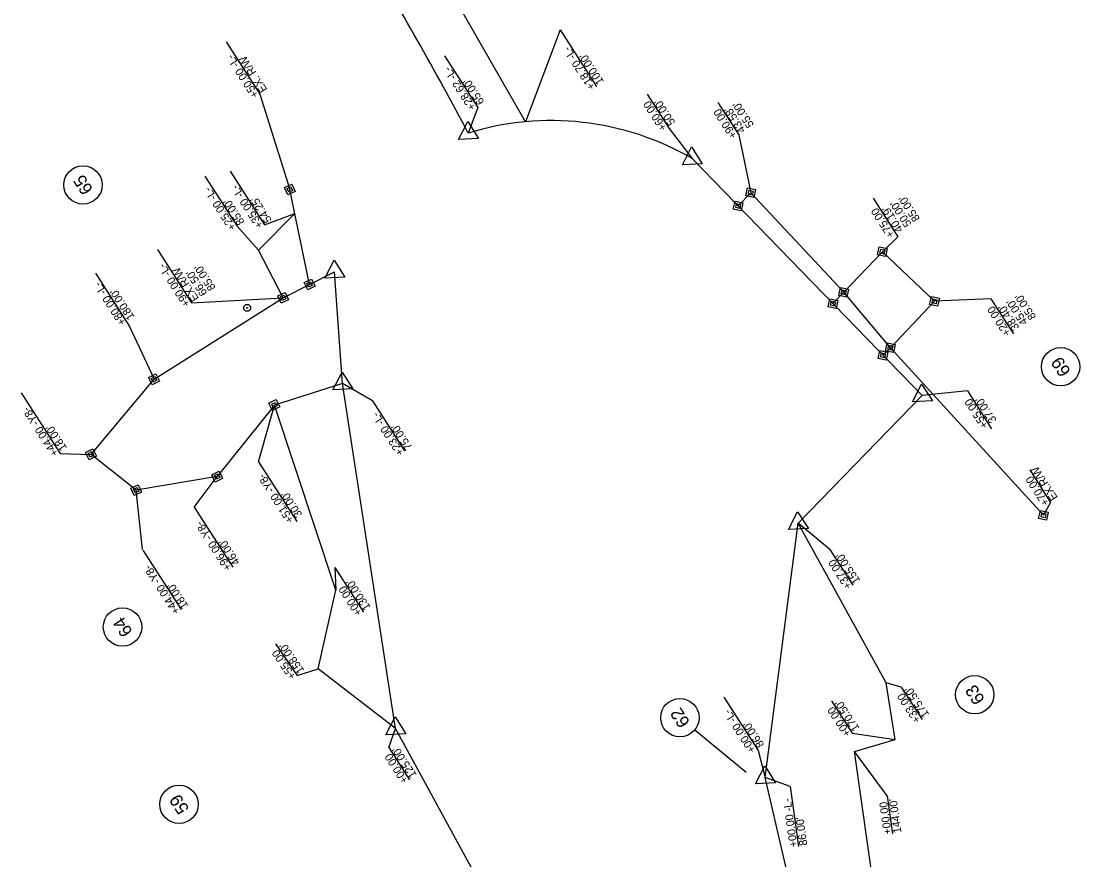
# Model space of a CAD drawing. Extents: x 474184 to 481900, y 489262 to 505659.
# Drawn here: x 477450 to 478112, y 499163 to 499687 of the extents above; entities that cross this region are included whole.
import ezdxf

# ---------------------------------------------------------------- set-up
doc = ezdxf.new("R2010")
doc.units = 0
for name, color, linetype in [('Default', 7, 'Continuous'), ('Prop Drainage Structure Drop Inlet Grate 2 Narrow Slots and Sag Grates 840 24 CELL', 7, 'Continuous'), ('Prop Drainage Structure Drop Inlet Grate 2 Wide Slots and Sag Grates 840 22 CELL', 7, 'Continuous'), ('Prop Drainage Structure Outlet Berm Ditch 850 10 CELL', 7, 'Continuous'), ('Prop Drainage Structure Outlet Berm Ditch 850 10 Label', 7, 'Continuous'), ('Prop Drainage Structure Outlet Generic CELL', 7, 'Continuous'), ('Prop Drainage Structure Pipe CSP 15in', 7, 'Continuous'), ('Prop Drainage Structure Pipe RCP 18in Class IV', 7, 'Continuous'), ('Prop Drainage Structure Pipe RCP 18in Class IV Label', 7, 'Continuous'), ('Prop Drainage Structure Pipe Side Drain 15in Label', 7, 'Continuous'), ('Prop Drainage Structure Pipe Stub Out CELL', 7, 'Continuous'), ('Prop Drainage Structure Plot Symbol 50 Scale', 7, 'Continuous'), ('Prop Earthen Structure Base Ditch Lateral Detail Label', 7, 'Continuous'), ('Prop Earthen Structure False Sump CELL', 7, 'Continuous'), ('Prop Earthen Structure False Sump Label', 7, 'Continuous')]:
    doc.layers.add(name, color=color, linetype=linetype)

msp = doc.modelspace()

# ---------------------------------------------------------------- linework, layer by layer
at = {"layer": 'Default'}
for radius in [2.18, 0.24]:
    msp.add_circle((477591.3, 499507.78), radius, dxfattribs=at)
at = {"layer": 'Prop Drainage Structure Drop Inlet Grate 2 Narrow Slots and Sag Grates 840 24 CELL'}
for p, q in [((477646.75, 499331.16), (477608.32, 499446.99)), ((477635.68, 499281.96), (477646.75, 499331.16)), ((477684.05, 499244.74), (477635.68, 499281.96))]:
    msp.add_line(p, q, dxfattribs=at)
at = {"layer": 'Prop Drainage Structure Drop Inlet Grate 2 Wide Slots and Sag Grates 840 22 CELL'}
for p, q in [((477988.26, 499542.87), (477964.13, 499517.52)), ((478020.86, 499511.85), (477988.26, 499542.87)), ((477613.8, 499514.07), (477645.97, 499530.3)), ((477533.09, 499463.09), (477613.8, 499514.07)), ((477993.28, 499482.87), (478020.86, 499511.85)), ((477493.72, 499416.16), (477533.09, 499463.09)), ((477650.93, 499460.41), (477608.32, 499446.99)), ((477608.32, 499446.99), (477572.54, 499402.26)), ((477521.92, 499393.79), (477493.72, 499416.16)), ((477572.54, 499402.26), (477521.92, 499393.79))]:
    msp.add_line(p, q, dxfattribs=at)
at = {"layer": 'Prop Drainage Structure Outlet Berm Ditch 850 10 CELL'}
for p, q in [((477646, 499345.46), (477663.96, 499317.47)), ((477609.09, 499297.77), (477622.61, 499277.88)), ((477622.61, 499277.88), (477635.68, 499281.96))]:
    msp.add_line(p, q, dxfattribs=at)
msp.add_lwpolyline([(477646, 499345.46), (477646.75, 499331.16)], dxfattribs=at)
at = {"layer": 'Prop Drainage Structure Outlet Berm Ditch 850 10 Label'}
for p, q in [((477630.32, 499522.4), (477617.99, 499581.8)), ((477906.01, 499579.74), (477898.14, 499571.47)), ((477964.13, 499517.52), (477906.01, 499579.74)), ((478088.97, 499378.08), (477993.28, 499482.87))]:
    msp.add_line(p, q, dxfattribs=at)
at = {"layer": 'Prop Drainage Structure Outlet Generic CELL'}
for p, q in [((477964.13, 499517.52), (477957.37, 499510.41)), ((477993.28, 499482.87), (477964.13, 499517.52)), ((477988.73, 499478.09), (477993.28, 499482.87))]:
    msp.add_line(p, q, dxfattribs=at)
at = {"layer": 'Prop Drainage Structure Pipe CSP 15in'}
for p, q in [((477488.71, 499584.64), (477488.71, 499584.64)), ((478099.68, 499470.97), (478099.68, 499470.97)), ((477513.41, 499308.18), (477513.41, 499308.18)), ((478046, 499265.84), (478046, 499265.84)), ((477861.73, 499251.47), (477861.73, 499251.47)), ((477870.99, 499243.84), (477903.14, 499217.42)), ((477548.71, 499197.34), (477548.71, 499197.34))]:
    msp.add_line(p, q, dxfattribs=at)
for centre in [(477488.71, 499584.64), (478099.68, 499470.97), (477513.41, 499308.18), (478046, 499265.84), (477861.73, 499251.47), (477548.71, 499197.34)]:
    msp.add_circle(centre, 12, dxfattribs=at)
at = {"layer": 'Prop Drainage Structure Pipe RCP 18in Class IV'}
for p, q in [((477729.47, 499617), (477729.47, 499617)), ((477869.34, 499601.16), (477869.34, 499601.16)), ((477617.99, 499581.8), (477617.99, 499581.8)), ((477906.01, 499579.74), (477906.01, 499579.74)), ((477898.14, 499571.47), (477898.14, 499571.47)), ((477988.26, 499542.87), (477988.26, 499542.87)), ((477645.97, 499530.3), (477645.97, 499530.3)), ((477630.32, 499522.4), (477630.32, 499522.4)), ((477613.8, 499514.07), (477613.8, 499514.07)), ((477964.13, 499517.52), (477964.13, 499517.52)), ((477957.37, 499510.41), (477957.37, 499510.41)), ((478020.86, 499511.85), (478020.86, 499511.85)), ((477993.28, 499482.87), (477993.28, 499482.87)), ((477988.73, 499478.09), (477988.73, 499478.09)), ((477533.09, 499463.09), (477533.09, 499463.09)), ((477650.93, 499460.41), (477650.93, 499460.41)), ((477608.32, 499446.99), (477608.32, 499446.99)), ((478013.12, 499452.95), (478013.12, 499452.95)), ((477493.72, 499416.16), (477493.72, 499416.16)), ((477572.54, 499402.26), (477572.54, 499402.26)), ((477521.92, 499393.79), (477521.92, 499393.79)), ((478088.97, 499378.08), (478088.97, 499378.08)), ((477935.65, 499373.12), (477935.65, 499373.12)), ((477684.05, 499244.74), (477684.05, 499244.74)), ((477915.07, 499214.11), (477915.07, 499214.11))]:
    msp.add_line(p, q, dxfattribs=at)
for points in [[(477729.13, 499624.21), (477735.87, 499613.71), (477723.41, 499613.1)], [(477869, 499608.36), (477875.74, 499597.86), (477863.28, 499597.25)], [(477645.63, 499537.5), (477652.37, 499527), (477639.91, 499526.39)], [(477650.59, 499467.62), (477657.33, 499457.12), (477644.87, 499456.51)], [(478012.78, 499460.15), (478019.52, 499449.65), (478007.05, 499449.04)], [(477935.31, 499380.32), (477942.05, 499369.82), (477929.59, 499369.21)], [(477683.71, 499251.95), (477690.45, 499241.45), (477677.98, 499240.84)], [(477914.74, 499221.31), (477921.47, 499210.81), (477909.01, 499210.2)]]:
    msp.add_lwpolyline(points, close=True, dxfattribs=at)
at = {"layer": 'Prop Drainage Structure Pipe RCP 18in Class IV Label'}
for points in [[(477616.82, 499578.39), (477614.59, 499582.97), (477619.16, 499585.2), (477621.4, 499580.63)], [(477617.41, 499580.1), (477616.29, 499582.38), (477618.58, 499583.5), (477619.69, 499581.21)], [(477902.98, 499577.8), (477904.06, 499582.77), (477909.04, 499581.68), (477907.95, 499576.71)], [(477904.49, 499578.77), (477905.04, 499581.26), (477907.52, 499580.71), (477906.98, 499578.23)], [(477895.11, 499569.53), (477896.19, 499574.5), (477901.17, 499573.41), (477900.08, 499568.44)], [(477896.62, 499570.5), (477897.17, 499572.99), (477899.65, 499572.44), (477899.11, 499569.96)], [(477985.23, 499540.93), (477986.32, 499545.9), (477991.29, 499544.81), (477990.21, 499539.84)], [(477986.75, 499541.9), (477987.29, 499544.39), (477989.78, 499543.84), (477989.23, 499541.36)], [(477629.15, 499519), (477626.91, 499523.57), (477631.49, 499525.8), (477633.72, 499521.23)], [(477629.73, 499520.7), (477628.62, 499522.99), (477630.9, 499524.1), (477632.02, 499521.81)], [(477961.1, 499515.57), (477962.19, 499520.55), (477967.16, 499519.46), (477966.08, 499514.49)], [(477612.63, 499510.66), (477610.4, 499515.24), (477614.97, 499517.47), (477617.2, 499512.89)], [(477613.21, 499512.36), (477612.1, 499514.65), (477614.39, 499515.77), (477615.5, 499513.48)], [(477954.34, 499508.47), (477955.43, 499513.44), (477960.4, 499512.36), (477959.31, 499507.38)], [(477962.62, 499516.55), (477963.16, 499519.03), (477965.65, 499518.49), (477965.1, 499516)], [(478017.83, 499509.9), (478018.91, 499514.88), (478023.89, 499513.79), (478022.8, 499508.82)], [(478019.34, 499510.87), (478019.89, 499513.36), (478022.37, 499512.82), (478021.83, 499510.33)], [(477955.85, 499509.44), (477956.4, 499511.93), (477958.88, 499511.38), (477958.34, 499508.9)], [(477985.7, 499476.14), (477986.78, 499481.12), (477991.76, 499480.03), (477990.67, 499475.06)], [(477987.21, 499477.12), (477987.76, 499479.6), (477990.24, 499479.06), (477989.7, 499476.57)], [(477990.25, 499480.93), (477991.34, 499485.9), (477996.31, 499484.82), (477995.22, 499479.84)], [(477991.76, 499481.9), (477992.31, 499484.39), (477994.79, 499483.84), (477994.25, 499481.36)], [(477531.92, 499459.69), (477529.68, 499464.27), (477534.26, 499466.5), (477536.49, 499461.92)], [(477532.5, 499461.39), (477531.39, 499463.68), (477533.67, 499464.79), (477534.79, 499462.51)], [(477607.15, 499443.59), (477604.92, 499448.16), (477609.49, 499450.39), (477611.72, 499445.82)], [(477607.73, 499445.29), (477606.62, 499447.58), (477608.91, 499448.69), (477610.02, 499446.4)], [(477492.55, 499412.76), (477490.32, 499417.33), (477494.89, 499419.56), (477497.13, 499414.99)], [(477493.14, 499414.46), (477492.02, 499416.75), (477494.31, 499417.86), (477495.42, 499415.58)], [(477571.37, 499398.86), (477569.14, 499403.43), (477573.71, 499405.66), (477575.94, 499401.09)], [(477571.95, 499400.56), (477570.84, 499402.85), (477573.13, 499403.96), (477574.24, 499401.67)], [(477520.75, 499390.38), (477518.52, 499394.96), (477523.1, 499397.19), (477525.33, 499392.61)], [(477521.34, 499392.08), (477520.22, 499394.37), (477522.51, 499395.49), (477523.63, 499393.2)], [(478085.94, 499376.14), (478087.02, 499381.11), (478091.99, 499380.03), (478090.91, 499375.05)], [(478087.45, 499377.11), (478087.99, 499379.6), (478090.48, 499379.05), (478089.94, 499376.57)]]:
    msp.add_lwpolyline(points, close=True, dxfattribs=at)
at = {"layer": 'Prop Drainage Structure Pipe Side Drain 15in Label'}
for p, q in [((478013.12, 499452.95), (477869.34, 499601.16)), ((477650.93, 499460.41), (477645.97, 499530.3)), ((477684.05, 499244.74), (477650.93, 499460.41)), ((477962.07, 499011.55), (477915.07, 499214.11))]:
    msp.add_line(p, q, dxfattribs=at)
for points in [[(477915.07, 499214.11), (477935.65, 499373.12), (478013.12, 499452.95)], [(477825.37, 498985.31), (477684.05, 499244.74)]]:
    msp.add_lwpolyline(points, dxfattribs=at)
for centre, radius, start, end in [((475792.47, 498595.18), 2190, 27.81302, 31.27221), ((477781.37, 499449.88), 175, 59.82147, 107.25033)]:
    msp.add_arc(centre, radius, start, end, dxfattribs=at)
at = {"layer": 'Prop Drainage Structure Pipe Stub Out CELL'}
for p, q in [((477765.25, 499624.13), (477677.9, 499776.71)), ((477598.42, 499543.94), (477621.09, 499566.86)), ((477613.8, 499514.07), (477598.42, 499543.94)), ((477990.73, 499273.38), (477935.65, 499373.12)), ((477996.2, 499237.76), (477990.73, 499273.38)), ((477970.76, 499230.34), (477996.2, 499237.76))]:
    msp.add_line(p, q, dxfattribs=at)
msp.add_lwpolyline([(477997.01, 499045.21), (477970.76, 499230.34)], dxfattribs=at)
at = {"layer": 'Prop Drainage Structure Plot Symbol 50 Scale'}
for p, q in [((477714.57, 499665.39), (477735.38, 499632.96)), ((477841.32, 499641.29), (477855.08, 499619.83)), ((477735.38, 499632.96), (477729.47, 499617)), ((477855.08, 499619.83), (477869.34, 499601.16)), ((478041.4, 499455.81), (478056.54, 499432.21)), ((477669.56, 499449.57), (477689.62, 499418.3)), ((477955.43, 499356.76), (477935.65, 499373.12)), ((477955.43, 499356.76), (477969.77, 499334.41)), ((477889.21, 499264.42), (477910.7, 499230.91)), ((477679.79, 499232.88), (477692.78, 499212.64)), ((477930.62, 499208.56), (477935.85, 499171))]:
    msp.add_line(p, q, dxfattribs=at)
for points in [[(477669.56, 499449.57), (477650.93, 499460.41)], [(478041.4, 499455.81), (478013.12, 499452.95)], [(477679.79, 499232.88), (477684.05, 499244.74)], [(477910.7, 499230.91), (477915.07, 499214.11)], [(477930.62, 499208.56), (477915.07, 499214.11)]]:
    msp.add_lwpolyline(points, dxfattribs=at)
at = {"layer": 'Prop Earthen Structure Base Ditch Lateral Detail Label'}
for p, q in [((477578.25, 499674.1), (477599.29, 499641.3)), ((477578.25, 499674.1), (477599.29, 499641.3)), ((477885.5, 499636.25), (477898.48, 499616.01)), ((478080.34, 499406.39), (478093.33, 499386.15))]:
    msp.add_line(p, q, dxfattribs=at)
for points in [[(477599.29, 499641.3), (477617.99, 499581.8)], [(477599.29, 499641.3), (477617.99, 499581.8)], [(477898.48, 499616.01), (477906.01, 499579.74)], [(478093.33, 499386.15), (478088.97, 499378.08)]]:
    msp.add_lwpolyline(points, dxfattribs=at)
at = {"layer": 'Prop Earthen Structure False Sump CELL'}
for p, q in [((477982.53, 499576.35), (477998.01, 499552.24)), ((477535.23, 499544.2), (477556.58, 499510.92)), ((477496.5, 499529.44), (477517.84, 499496.16)), ((478056.04, 499513.51), (478070.18, 499491.47)), ((477517.84, 499496.16), (477533.09, 499463.09)), ((477450.07, 499454.7), (477474.44, 499416.7)), ((477598.29, 499411.53), (477622.29, 499374.13)), ((477558.19, 499383.22), (477572.54, 499402.26)), ((477525.89, 499356.76), (477521.92, 499393.79)), ((477558.19, 499383.22), (477582.29, 499345.65)), ((477526.17, 499356.31), (477550.07, 499319.06))]:
    msp.add_line(p, q, dxfattribs=at)
for points in [[(477998.01, 499552.24), (477988.26, 499542.87)], [(477556.58, 499510.92), (477613.8, 499514.07)], [(478056.04, 499513.51), (478020.86, 499511.85)], [(477598.29, 499411.53), (477608.32, 499446.99)], [(477474.44, 499416.7), (477493.72, 499416.16)]]:
    msp.add_lwpolyline(points, dxfattribs=at)
at = {"layer": 'Prop Earthen Structure False Sump Label'}
for p, q in [((477786.97, 499681.66), (477809.68, 499646.27)), ((477580.75, 499593.14), (477602.16, 499559.77)), ((477564.9, 499590.17), (477585.03, 499558.8)), ((477602.16, 499559.77), (477621.09, 499566.86)), ((477585.03, 499558.8), (477598.42, 499543.94)), ((478000.07, 499270.63), (478013.05, 499250.39)), ((477956.46, 499262.12), (477969.45, 499241.88)), ((477991.37, 499202.68), (477994.68, 499178.86))]:
    msp.add_line(p, q, dxfattribs=at)
for points in [[(477786.97, 499681.66), (477765.25, 499624.13)], [(478000.07, 499270.63), (477990.73, 499273.38)], [(477969.45, 499241.88), (477996.2, 499237.76)], [(477991.37, 499202.68), (477970.76, 499230.34)]]:
    msp.add_lwpolyline(points, dxfattribs=at)

# ---------------------------------------------------------------- texts
at = {"layer": 'Prop Drainage Structure Outlet Berm Ditch 850 10 CELL'}
for s, rotation, p in [("130.00'", 122.68181, (477668.7, 499320.51)), ('+00.00', 122.68181, (477663.44, 499317.13)), ("158.00'", 124.20099, (477627.26, 499281.04)), ('+55.00', 124.20099, (477622.09, 499277.53))]:
    msp.add_text(s, height=5, rotation=rotation, dxfattribs=at).set_placement(p)
at = {"layer": 'Prop Drainage Structure Pipe CSP 15in'}
for s, p in [('65', (477495.3, 499581.78)), ('69', (478106.33, 499468)), ('64', (477520.04, 499305.26)), ('63', (478052.66, 499262.87)), ('62', (477868.38, 499248.51)), ('59', (477555.33, 499194.43))]:
    msp.add_text(s, height=8, rotation=122.68181, dxfattribs=at).set_placement(p)
at = {"layer": 'Prop Drainage Structure Plot Symbol 50 Scale'}
for s, rotation, p in [('+28.62 -L-', 122.68181, (477734.49, 499633.26)), ("65.00'", 122.68181, (477739.75, 499636.63)), ('+60.00', 122.68181, (477853.84, 499620.38)), ("50.00'", 122.68181, (477859.1, 499623.75)), ('+55.00 ', 122.68181, (478054.61, 499434.25)), ("37.00'", 122.68181, (478059.87, 499437.63)), ('+23.00 -L-', 122.68181, (477689.53, 499417.28)), ("75.00'", 122.68181, (477694.79, 499420.65)), ('+37.00 ', 122.68181, (477969.46, 499333.76)), ("155.00'", 122.68181, (477974.72, 499337.14)), ('+00.00 -L-', 122.68181, (477909.37, 499231.33)), ("86.00'", 122.68181, (477914.63, 499234.7)), ('+00.00', 122.68181, (477692.25, 499212.3)), ("125.00'", 122.68181, (477697.51, 499215.68)), ('+00.00 -L-', 97.92268, (477935.23, 499170.91)), ("86.00'", 97.92268, (477941.42, 499171.78))]:
    msp.add_text(s, height=5, rotation=rotation, dxfattribs=at).set_placement(p)
at = {"layer": 'Prop Earthen Structure Base Ditch Lateral Detail Label'}
for s, p in [('+50.00 -L-', (477598.76, 499640.97)), ('+50.00 -L-', (477598.76, 499640.97)), ('EX. R/W', (477604.02, 499644.34)), ('EX. R/W', (477604.02, 499644.34)), ('+90.00', (477897.69, 499615.5)), ("43.58'", (477902.95, 499618.88)), ("55.00'", (477908.21, 499622.25)), ('EX.R/W', (478098.06, 499389.18)), ('+70.00', (478092.8, 499385.81))]:
    msp.add_text(s, height=5, rotation=122.68181, dxfattribs=at).set_placement(p)
at = {"layer": 'Prop Earthen Structure False Sump CELL'}
for s, p in [("50.00'", (478006.71, 499560.2)), ("85.00'", (478011.98, 499563.57)), ('+75.00 ', (477996.19, 499553.45)), ("40.19'", (478001.45, 499556.82)), ('+90.00 -L-', (477556.04, 499510.31)), ('EX.R/W', (477561.31, 499513.69)), ("85.00'", (477571.83, 499520.43)), ("66.50'", (477566.57, 499517.06)), ('+80.00 -L-', (477515.86, 499498.74)), ("180.00'", (477521.12, 499502.12)), ("85.00'", (478084.6, 499502.19)), ('+20.00', (478068.82, 499492.06)), ("38.40'", (478074.08, 499495.44)), ("45.00'", (478079.34, 499498.81)), ('+44.00 -Y8-', (477473.63, 499416.84)), ("18.00'", (477478.9, 499420.21)), ('+51.00 -Y8-', (477620.74, 499375.13)), ("30.00'", (477626, 499378.5)), ('+96.00 -Y8-', (477581.79, 499345.32)), ("46.00'", (477587.05, 499348.69)), ('+44.00 -Y8-', (477549.5, 499318.05)), ("18.00'", (477554.76, 499321.43))]:
    msp.add_text(s, height=5, rotation=122.68181, dxfattribs=at).set_placement(p)
at = {"layer": 'Prop Earthen Structure False Sump Label'}
for s, rotation, p in [('+18.70 -L-', 122.68181, (477809.15, 499645.94)), ("100.00'", 122.68181, (477814.41, 499649.31)), ('+25.00 -L-', 122.68181, (477584.61, 499558.08)), ('+35.00 -L- ', 122.68181, (477601.61, 499559.42)), ("85.00'", 122.68181, (477589.87, 499561.45)), ("54.25'", 122.68181, (477606.87, 499562.79)), ("175.50'", 122.68181, (478017.78, 499253.43)), ("170.50'", 122.68181, (477974.18, 499244.92)), ('+33.00', 122.68181, (478012.52, 499250.06)), ('+00.00', 122.68181, (477968.92, 499241.55)), ('+00.00', 97.92268, (477994.06, 499178.78)), ("144.00'", 97.92268, (478000.25, 499179.64))]:
    msp.add_text(s, height=5, rotation=rotation, dxfattribs=at).set_placement(p)

doc.saveas('drawing.dxf')
